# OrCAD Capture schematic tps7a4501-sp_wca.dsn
size B
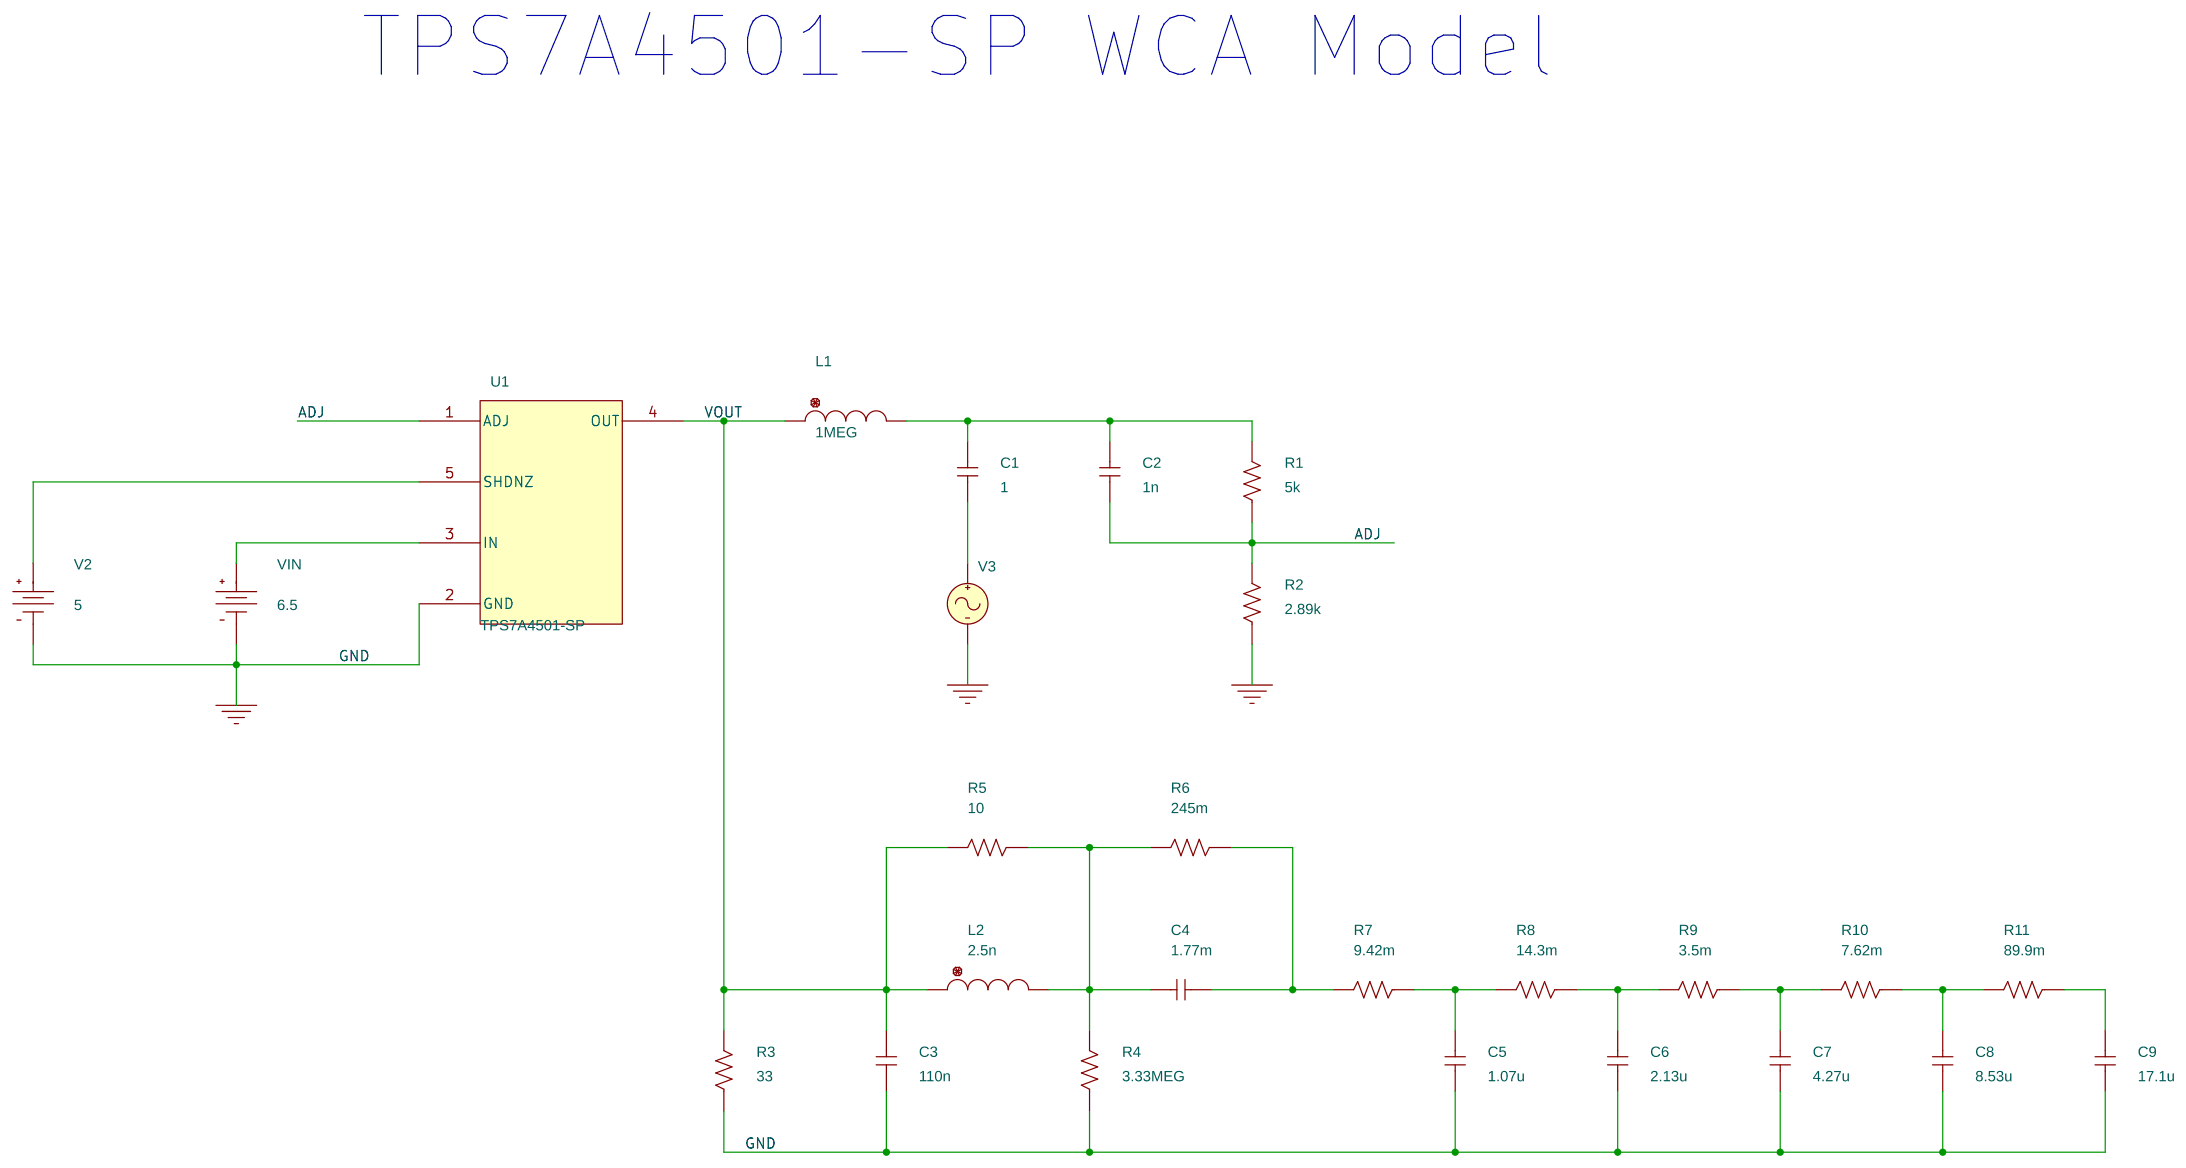
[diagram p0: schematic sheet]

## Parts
C1  1  [cap196]
C2  1n  [cap196]
C3  110n  [cap196]
C4  1.77m  [cap196]
C5  1.07u  [cap196]
C6  2.13u  [cap196]
C7  4.27u  [cap196]
C8  8.53u  [cap196]
C9  17.1u  [cap196]
L1  1MEG  [DISC350x175LS200x100034]
L2  2.5n  [DISC350x175LS200x100034]
R1  5k  [AXRC05]
R2  2.89k  [AXRC05]
R3  33  [AXRC05]
R4  3.33MEG  [AXRC05]
R5  10  [AXRC05]
R6  245m  [AXRC05]
R7  9.42m  [AXRC05]
R8  14.3m  [AXRC05]
R9  3.5m  [AXRC05]
R10  7.62m  [AXRC05]
R11  89.9m  [AXRC05]
U1  TPS7A4501-SP
V2  VDC
V3  VAC
VIN  VDC

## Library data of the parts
C1-C9 = C
L1 L2 = L
R1-R11 = R
U1 = TPS7A4501-SP_1: PSpiceTemplate: X^@REFDES  %ADJ %GND %IN %OUT %SHDNZ @MODEL
V2 = VDC: DC: 5
V3 = VAC
VIN = VDC: DC: 6.5

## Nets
0: C3.1 C5.1 C6.1 C7.1 C8.1 C9.1 R2.1 R3.1 R4.1 U1.2(GND) V2.1(-) V3.2(-) VIN.1(-)
ADJ: C2.1 R1.1 R2.2 U1.1(ADJ)
VOUT: C3.2 L1.1 L2.1 R3.2 R5.2 U1.4(OUT)
N00232: U1.3(IN) VIN.0(+)
N00260: U1.5(SHDNZ) V2.0(+)
N00550: C1.1 V3.1(+)
N00558: C1.2 C2.2 L1.2 R1.2
N01425: C4.2 L2.2 R4.2 R5.1 R6.2
N01518: C4.1 R6.1 R7.2
N02125: C5.2 R7.1 R8.2
N02129: C6.2 R8.1 R9.2
N02133: C7.2 R9.1 R10.2
N02137: C8.2 R10.1 R11.2
N02141: C9.2 R11.1

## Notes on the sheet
- TPS7A4501-SP WCA Model
